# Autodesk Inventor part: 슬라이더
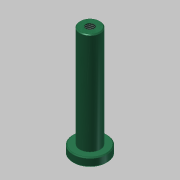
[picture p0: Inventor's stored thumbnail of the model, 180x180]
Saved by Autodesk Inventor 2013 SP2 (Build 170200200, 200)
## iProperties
Created: 2016-02
Part Number: 슬라이더
Material: 스테인리스강
Document SubType Name: Modeling
Designer: mduedu
Density: 8.08 g/cm^3
Author: mduedu
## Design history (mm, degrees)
sketch "스케치1"
  geometry: C1 r 10 at (0, 0); 1 further point
  constraints: 1 centre point, 1 coincident
  dimensions: "d0" = 20 diameter of C1
extrude "돌출1" new body sketch "스케치1" distance "d1" = 5; taper "d2" = 0 deg
sketch "스케치2"
  geometry: C1 r 6 at (0, 0); 1 further point
  constraints: 1 centre point, 1 coincident
  dimensions: "d3" = 12 diameter of C1
extrude "돌출2" join sketch "스케치2" distance "d4" = 60; taper "d5" = 0 deg
chamfer "모따기1" distance "d6" = 0.5; stored, may be unused: second distance "d7" = 2, angle "d8" = 45 deg
hole "구멍1" diameter "d11" = 4.917; stored, may be unused: countersink angle "d15" = 90 deg, drill point angle "d17" = 118 deg; dims "d9" = 10, "d10" = 10, "d12" = 10, "d13" = 4, "d14" = 2, "d16" = 12
chamfer "모따기2" distance "d18" = 0.5; stored, may be unused: second distance "d19" = 2, angle "d20" = 45 deg
node "솔리드1"
